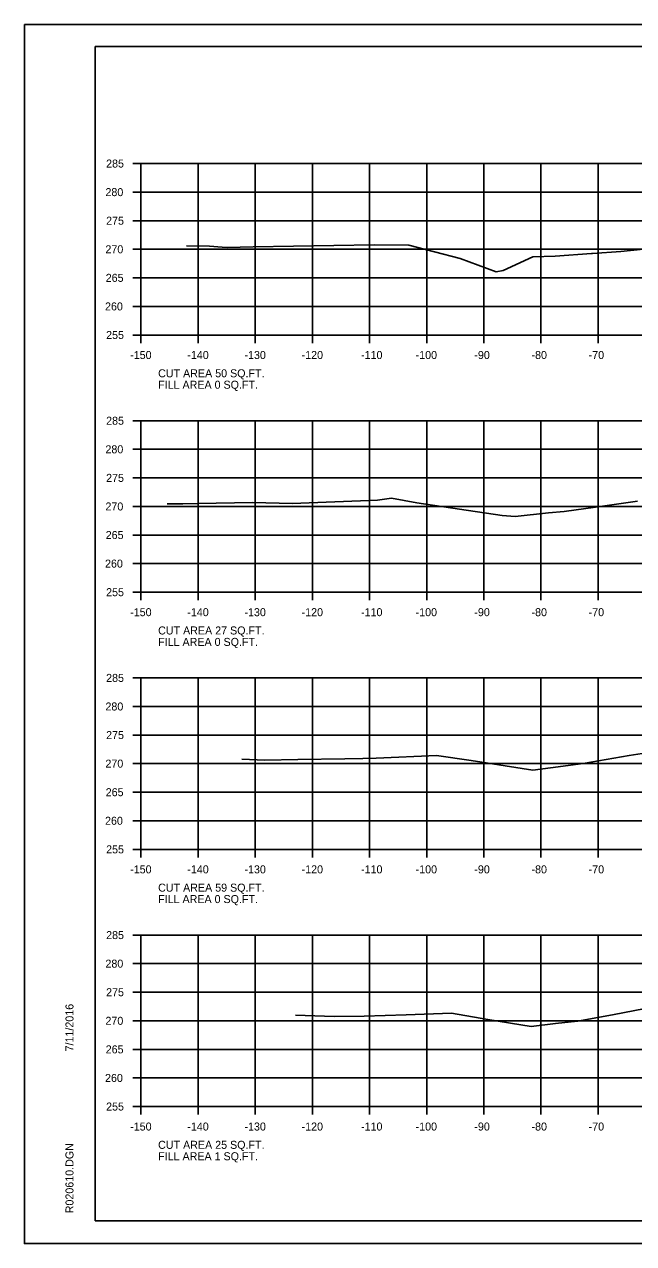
# Model space of a CAD drawing. Extents: x 1103485 to 1107180, y 2010593 to 2011873.
# Drawn here: x 1106846.8 to 1106953.4, y 2010592.8 to 2010806.2 of the extents above; entities that cross this region are included whole.
import ezdxf

# ---------------------------------------------------------------- set-up
doc = ezdxf.new("R2010")
doc.units = 0
for name, color, linetype in [('R_Axis', 7, 'Continuous'), ('R_Axis Annot', 7, 'Continuous'), ('R_Border', 7, 'Continuous'), ('R_Exist Surface', 7, 'Continuous'), ('R_Grid', 7, 'Continuous'), ('R_No Plot', 7, 'Continuous')]:
    doc.layers.add(name, color=color, linetype=linetype)

msp = doc.modelspace()

# ---------------------------------------------------------------- linework, layer by layer
at = {"layer": 'R_Axis'}
for p, q in [((1106865.78, 2010781.82), (1106867.18, 2010781.82)), ((1106867.18, 2010751.82), (1106867.18, 2010781.82)), ((1106865.78, 2010776.82), (1106867.18, 2010776.82)), ((1106865.78, 2010771.82), (1106867.18, 2010771.82)), ((1106865.78, 2010766.82), (1106867.18, 2010766.82)), ((1106865.78, 2010761.82), (1106867.18, 2010761.82)), ((1106865.78, 2010756.82), (1106867.18, 2010756.82)), ((1106865.78, 2010751.82), (1106867.18, 2010751.82)), ((1106867.18, 2010751.82), (1107167.18, 2010751.82)), ((1106867.18, 2010750.42), (1106867.18, 2010751.82)), ((1106877.18, 2010750.42), (1106877.18, 2010751.82)), ((1106887.18, 2010750.42), (1106887.18, 2010751.82)), ((1106897.18, 2010750.42), (1106897.18, 2010751.82)), ((1106907.18, 2010750.42), (1106907.18, 2010751.82)), ((1106917.18, 2010750.42), (1106917.18, 2010751.82)), ((1106927.18, 2010750.42), (1106927.18, 2010751.82)), ((1106937.18, 2010750.42), (1106937.18, 2010751.82)), ((1106947.18, 2010750.42), (1106947.18, 2010751.82)), ((1106865.78, 2010736.82), (1106867.18, 2010736.82)), ((1106867.18, 2010706.82), (1106867.18, 2010736.82)), ((1106865.78, 2010731.82), (1106867.18, 2010731.82)), ((1106865.78, 2010726.82), (1106867.18, 2010726.82)), ((1106865.78, 2010721.82), (1106867.18, 2010721.82)), ((1106865.78, 2010716.82), (1106867.18, 2010716.82)), ((1106865.78, 2010711.82), (1106867.18, 2010711.82)), ((1106865.78, 2010706.82), (1106867.18, 2010706.82)), ((1106867.18, 2010706.82), (1107167.18, 2010706.82)), ((1106867.18, 2010705.42), (1106867.18, 2010706.82)), ((1106877.18, 2010705.42), (1106877.18, 2010706.82)), ((1106887.18, 2010705.42), (1106887.18, 2010706.82)), ((1106897.18, 2010705.42), (1106897.18, 2010706.82)), ((1106907.18, 2010705.42), (1106907.18, 2010706.82)), ((1106917.18, 2010705.42), (1106917.18, 2010706.82)), ((1106927.18, 2010705.42), (1106927.18, 2010706.82)), ((1106937.18, 2010705.42), (1106937.18, 2010706.82)), ((1106947.18, 2010705.42), (1106947.18, 2010706.82)), ((1106865.78, 2010691.82), (1106867.18, 2010691.82)), ((1106867.18, 2010661.82), (1106867.18, 2010691.82)), ((1106865.78, 2010686.82), (1106867.18, 2010686.82)), ((1106865.78, 2010681.82), (1106867.18, 2010681.82)), ((1106865.78, 2010676.82), (1106867.18, 2010676.82)), ((1106865.78, 2010671.82), (1106867.18, 2010671.82)), ((1106865.78, 2010666.82), (1106867.18, 2010666.82)), ((1106865.78, 2010661.82), (1106867.18, 2010661.82)), ((1106867.18, 2010661.82), (1107167.18, 2010661.82)), ((1106867.18, 2010660.42), (1106867.18, 2010661.82)), ((1106877.18, 2010660.42), (1106877.18, 2010661.82)), ((1106887.18, 2010660.42), (1106887.18, 2010661.82)), ((1106897.18, 2010660.42), (1106897.18, 2010661.82)), ((1106907.18, 2010660.42), (1106907.18, 2010661.82)), ((1106917.18, 2010660.42), (1106917.18, 2010661.82)), ((1106927.18, 2010660.42), (1106927.18, 2010661.82)), ((1106937.18, 2010660.42), (1106937.18, 2010661.82)), ((1106947.18, 2010660.42), (1106947.18, 2010661.82)), ((1106865.78, 2010646.82), (1106867.18, 2010646.82)), ((1106867.18, 2010616.82), (1106867.18, 2010646.82)), ((1106865.78, 2010641.82), (1106867.18, 2010641.82)), ((1106865.78, 2010636.82), (1106867.18, 2010636.82)), ((1106865.78, 2010631.82), (1106867.18, 2010631.82)), ((1106865.78, 2010626.82), (1106867.18, 2010626.82)), ((1106865.78, 2010621.82), (1106867.18, 2010621.82)), ((1106865.78, 2010616.82), (1106867.18, 2010616.82)), ((1106867.18, 2010616.82), (1107167.18, 2010616.82)), ((1106867.18, 2010615.42), (1106867.18, 2010616.82)), ((1106877.18, 2010615.42), (1106877.18, 2010616.82)), ((1106887.18, 2010615.42), (1106887.18, 2010616.82)), ((1106897.18, 2010615.42), (1106897.18, 2010616.82)), ((1106907.18, 2010615.42), (1106907.18, 2010616.82)), ((1106917.18, 2010615.42), (1106917.18, 2010616.82)), ((1106927.18, 2010615.42), (1106927.18, 2010616.82)), ((1106937.18, 2010615.42), (1106937.18, 2010616.82)), ((1106947.18, 2010615.42), (1106947.18, 2010616.82))]:
    msp.add_line(p, q, dxfattribs=at)
at = {"layer": 'R_Border'}
for p, q in [((1106859.18, 2010802.28), (1107175.36, 2010802.28)), ((1106859.18, 2010596.82), (1106859.18, 2010802.28)), ((1106859.18, 2010596.82), (1106859.18, 2010596.82)), ((1107175.36, 2010596.82), (1106859.18, 2010596.82))]:
    msp.add_line(p, q, dxfattribs=at)
at = {"layer": 'R_Exist Surface'}
for points in [[(1106875.17, 2010767.43), (1106879.18, 2010767.38), (1106881.4, 2010767.19), (1106882.27, 2010767.11), (1106886.83, 2010767.23), (1106907.99, 2010767.61), (1106914.03, 2010767.53), (1106923.03, 2010765.18), (1106929.32, 2010762.86), (1106930.55, 2010763.11), (1106935.78, 2010765.5), (1106939.67, 2010765.6), (1106946.01, 2010766.1), (1106946.2, 2010766.11), (1106951.15, 2010766.45), (1106955.12, 2010766.83)], [(1106871.75, 2010722.26), (1106872.06, 2010722.25), (1106872.5, 2010722.25), (1106873.71, 2010722.27), (1106874.5, 2010722.29), (1106877.11, 2010722.34), (1106886.78, 2010722.53), (1106893.61, 2010722.35), (1106908.59, 2010722.92), (1106911, 2010723.27), (1106915.45, 2010722.47), (1106930.36, 2010720.26), (1106932.66, 2010720.09), (1106938.47, 2010720.7), (1106941.23, 2010720.96), (1106946.71, 2010721.7), (1106954.05, 2010722.75)], [(1106884.82, 2010677.59), (1106888.86, 2010677.44), (1106894.65, 2010677.53), (1106902.85, 2010677.66), (1106906.01, 2010677.69), (1106908.31, 2010677.78), (1106918.88, 2010678.27), (1106924.97, 2010677.35), (1106935.76, 2010675.69), (1106941.94, 2010676.51), (1106944.54, 2010676.84), (1106952.63, 2010678.25), (1106954.9, 2010678.62)], [(1106894.24, 2010632.83), (1106900.97, 2010632.59), (1106906.21, 2010632.66), (1106913.58, 2010632.86), (1106921.53, 2010633.13), (1106927.85, 2010632.07), (1106935.47, 2010630.85), (1106939.71, 2010631.34), (1106943.58, 2010631.73), (1106949.69, 2010632.86), (1106955.43, 2010633.96)]]:
    msp.add_lwpolyline(points, dxfattribs=at)
at = {"layer": 'R_Grid'}
for p, q in [((1106867.18, 2010781.82), (1107167.18, 2010781.82)), ((1106867.18, 2010751.82), (1106867.18, 2010781.82)), ((1106877.18, 2010751.82), (1106877.18, 2010781.82)), ((1106887.18, 2010751.82), (1106887.18, 2010781.82)), ((1106897.18, 2010751.82), (1106897.18, 2010781.82)), ((1106907.18, 2010751.82), (1106907.18, 2010781.82)), ((1106917.18, 2010751.82), (1106917.18, 2010781.82)), ((1106927.18, 2010751.82), (1106927.18, 2010781.82)), ((1106937.18, 2010751.82), (1106937.18, 2010781.82)), ((1106947.18, 2010751.82), (1106947.18, 2010781.82)), ((1106867.18, 2010776.82), (1107167.18, 2010776.82)), ((1106867.18, 2010771.82), (1107167.18, 2010771.82)), ((1106867.18, 2010766.82), (1107167.18, 2010766.82)), ((1106867.18, 2010761.82), (1107167.18, 2010761.82)), ((1106867.18, 2010756.82), (1107167.18, 2010756.82)), ((1106867.18, 2010751.82), (1107167.18, 2010751.82)), ((1106867.18, 2010736.82), (1107167.18, 2010736.82)), ((1106867.18, 2010706.82), (1106867.18, 2010736.82)), ((1106877.18, 2010706.82), (1106877.18, 2010736.82)), ((1106887.18, 2010706.82), (1106887.18, 2010736.82)), ((1106897.18, 2010706.82), (1106897.18, 2010736.82)), ((1106907.18, 2010706.82), (1106907.18, 2010736.82)), ((1106917.18, 2010706.82), (1106917.18, 2010736.82)), ((1106927.18, 2010706.82), (1106927.18, 2010736.82)), ((1106937.18, 2010706.82), (1106937.18, 2010736.82)), ((1106947.18, 2010706.82), (1106947.18, 2010736.82)), ((1106867.18, 2010731.82), (1107167.18, 2010731.82)), ((1106867.18, 2010726.82), (1107167.18, 2010726.82)), ((1106867.18, 2010721.82), (1107167.18, 2010721.82)), ((1106867.18, 2010716.82), (1107167.18, 2010716.82)), ((1106867.18, 2010711.82), (1107167.18, 2010711.82)), ((1106867.18, 2010706.82), (1107167.18, 2010706.82)), ((1106867.18, 2010691.82), (1107167.18, 2010691.82)), ((1106867.18, 2010661.82), (1106867.18, 2010691.82)), ((1106877.18, 2010661.82), (1106877.18, 2010691.82)), ((1106887.18, 2010661.82), (1106887.18, 2010691.82)), ((1106897.18, 2010661.82), (1106897.18, 2010691.82)), ((1106907.18, 2010661.82), (1106907.18, 2010691.82)), ((1106917.18, 2010661.82), (1106917.18, 2010691.82)), ((1106927.18, 2010661.82), (1106927.18, 2010691.82)), ((1106937.18, 2010661.82), (1106937.18, 2010691.82)), ((1106947.18, 2010661.82), (1106947.18, 2010691.82)), ((1106867.18, 2010686.82), (1107167.18, 2010686.82)), ((1106867.18, 2010681.82), (1107167.18, 2010681.82)), ((1106867.18, 2010676.82), (1107167.18, 2010676.82)), ((1106867.18, 2010671.82), (1107167.18, 2010671.82)), ((1106867.18, 2010666.82), (1107167.18, 2010666.82)), ((1106867.18, 2010661.82), (1107167.18, 2010661.82)), ((1106867.18, 2010646.82), (1107167.18, 2010646.82)), ((1106867.18, 2010616.82), (1106867.18, 2010646.82)), ((1106877.18, 2010616.82), (1106877.18, 2010646.82)), ((1106887.18, 2010616.82), (1106887.18, 2010646.82)), ((1106897.18, 2010616.82), (1106897.18, 2010646.82)), ((1106907.18, 2010616.82), (1106907.18, 2010646.82)), ((1106917.18, 2010616.82), (1106917.18, 2010646.82)), ((1106927.18, 2010616.82), (1106927.18, 2010646.82)), ((1106937.18, 2010616.82), (1106937.18, 2010646.82)), ((1106947.18, 2010616.82), (1106947.18, 2010646.82)), ((1106867.18, 2010641.82), (1107167.18, 2010641.82)), ((1106867.18, 2010636.82), (1107167.18, 2010636.82)), ((1106867.18, 2010631.82), (1107167.18, 2010631.82)), ((1106867.18, 2010626.82), (1107167.18, 2010626.82)), ((1106867.18, 2010621.82), (1107167.18, 2010621.82)), ((1106867.18, 2010616.82), (1107167.18, 2010616.82))]:
    msp.add_line(p, q, dxfattribs=at)
at = {"layer": 'R_No Plot'}
for p, q in [((1106846.78, 2010806.17), (1107180.12, 2010806.17)), ((1106846.78, 2010592.84), (1107180.12, 2010592.84))]:
    msp.add_line(p, q, dxfattribs=at)
for points in [[(1106846.78, 2010806.17), (1107180.12, 2010806.17), (1107180.12, 2010592.83), (1106846.78, 2010592.83)], [(1107093.1, 2010802.28), (1107093.1, 2010792.4), (1107128.84, 2010792.4), (1107128.84, 2010789.48), (1107152.04, 2010789.48), (1107152.04, 2010765.14), (1107175.36, 2010765.14), (1107175.36, 2010596.82), (1106859.18, 2010596.82), (1106859.18, 2010802.28)]]:
    msp.add_lwpolyline(points, close=True, dxfattribs=at)

# ---------------------------------------------------------------- texts
at = {"layer": 'R_Axis Annot'}
for s, p in [('285', (1106861.08, 2010781.12)), ('280', (1106860.96, 2010776.12)), ('275', (1106861.08, 2010771.12)), ('270', (1106860.96, 2010766.12)), ('265', (1106861.01, 2010761.12)), ('260', (1106860.89, 2010756.12)), ('255', (1106861.08, 2010751.12)), ('-150', (1106865.29, 2010747.62)), ('-140', (1106875.29, 2010747.62)), ('-130', (1106885.29, 2010747.62)), ('-120', (1106895.29, 2010747.62)), ('-110', (1106905.69, 2010747.62)), ('-100', (1106915.24, 2010747.62)), ('-90', (1106925.52, 2010747.62)), ('-80', (1106935.52, 2010747.62)), ('-70', (1106945.52, 2010747.62)), ('CUT AREA 50 SQ.FT.', (1106870.18, 2010744.42)), ('FILL AREA 0 SQ.FT.', (1106870.18, 2010742.42)), ('285', (1106861.08, 2010736.12)), ('280', (1106860.96, 2010731.12)), ('275', (1106861.08, 2010726.12)), ('270', (1106860.96, 2010721.12)), ('265', (1106861.01, 2010716.12)), ('260', (1106860.89, 2010711.12)), ('255', (1106861.08, 2010706.12)), ('-150', (1106865.29, 2010702.62)), ('-140', (1106875.29, 2010702.62)), ('-130', (1106885.29, 2010702.62)), ('-120', (1106895.29, 2010702.62)), ('-110', (1106905.69, 2010702.62)), ('-100', (1106915.24, 2010702.62)), ('-90', (1106925.52, 2010702.62)), ('-80', (1106935.52, 2010702.62)), ('-70', (1106945.52, 2010702.62)), ('CUT AREA 27 SQ.FT.', (1106870.18, 2010699.42)), ('FILL AREA 0 SQ.FT.', (1106870.18, 2010697.42)), ('285', (1106861.08, 2010691.12)), ('280', (1106860.96, 2010686.12)), ('275', (1106861.08, 2010681.12)), ('270', (1106860.96, 2010676.12)), ('265', (1106861.01, 2010671.12)), ('260', (1106860.89, 2010666.12)), ('255', (1106861.08, 2010661.12)), ('-150', (1106865.29, 2010657.62)), ('-140', (1106875.29, 2010657.62)), ('-130', (1106885.29, 2010657.62)), ('-120', (1106895.29, 2010657.62)), ('-110', (1106905.69, 2010657.62)), ('-100', (1106915.24, 2010657.62)), ('-90', (1106925.52, 2010657.62)), ('-80', (1106935.52, 2010657.62)), ('-70', (1106945.52, 2010657.62)), ('CUT AREA 59 SQ.FT.', (1106870.18, 2010654.42)), ('FILL AREA 0 SQ.FT.', (1106870.18, 2010652.42)), ('285', (1106861.08, 2010646.12)), ('280', (1106860.96, 2010641.12)), ('275', (1106861.08, 2010636.12)), ('270', (1106860.96, 2010631.12)), ('265', (1106861.01, 2010626.12)), ('260', (1106860.89, 2010621.12)), ('255', (1106861.08, 2010616.12)), ('-150', (1106865.29, 2010612.62)), ('-140', (1106875.29, 2010612.62)), ('-130', (1106885.29, 2010612.62)), ('-120', (1106895.29, 2010612.62)), ('-110', (1106905.69, 2010612.62)), ('-100', (1106915.24, 2010612.62)), ('-90', (1106925.52, 2010612.62)), ('-80', (1106935.52, 2010612.62)), ('-70', (1106945.52, 2010612.62)), ('CUT AREA 25 SQ.FT.', (1106870.18, 2010609.42)), ('FILL AREA 1 SQ.FT.', (1106870.18, 2010607.42))]:
    msp.add_text(s, height=1.4, dxfattribs=at).set_placement(p)
at = {"layer": 'R_Border'}
for s, p in [('7/11/2016', (1106855.37, 2010626.46)), ('R020610.DGN', (1106855.37, 2010598.14))]:
    msp.add_text(s, height=1.4, rotation=90, dxfattribs=at).set_placement(p)

doc.saveas('drawing.dxf')
